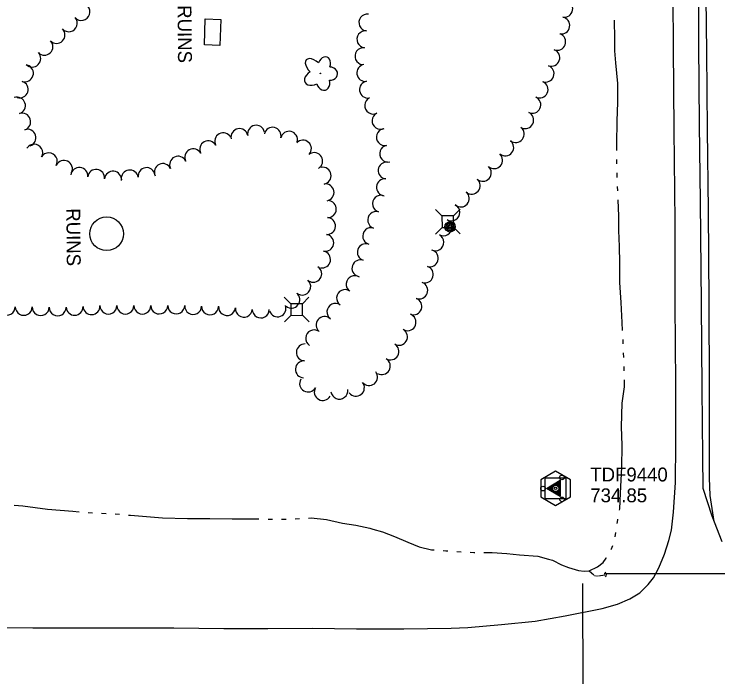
# Model space of a CAD drawing. Extents: x 589250 to 1188077, y 162953 to 363065.
# Drawn here: x 593849.7 to 594153.6, y 165056 to 165342.4 of the extents above; entities that cross this region are included whole.
import ezdxf

# ---------------------------------------------------------------- set-up
doc = ezdxf.new("R2010")
doc.units = 0
for name, color, linetype in [('E_BLD_HvyDash', 7, 'Continuous'), ('E_BLD_Text', 7, 'Continuous'), ('E_DRN', 7, 'Continuous'), ('E_DRN_Pipe', 7, 'Continuous'), ('E_LAND_TreeLine_P', 7, 'Continuous'), ('E_LAND_Vegetation', 7, 'Continuous'), ('E_MAP_Control', 7, 'Continuous'), ('E_MARK', 7, 'Continuous'), ('E_MISCPROP', 7, 'Continuous'), ('E_RDWY', 7, 'Continuous'), ('E_RDWY_Gravel', 7, 'Continuous'), ('E_UTL_AG_Bold', 7, 'Continuous'), ('E_WTR_FlowLine', 7, 'Continuous')]:
    doc.layers.add(name, color=color, linetype=linetype)

msp = doc.modelspace()

# ---------------------------------------------------------------- linework, layer by layer
at = {"layer": 'E_BLD_HvyDash'}
for p, q in [((593931.82, 165329.04), (593932.22, 165340.3)), ((593932.22, 165340.3), (593938.97, 165340.06)), ((593938.97, 165340.06), (593938.57, 165328.8)), ((593938.57, 165328.8), (593931.82, 165329.04))]:
    msp.add_line(p, q, dxfattribs=at)
msp.add_circle((593889.63, 165247.45), 7.29, dxfattribs=at)
at = {"layer": 'E_DRN'}
msp.add_arc((594104.16, 165100.16), 1.29, 311.5769, 57.8372, dxfattribs=at)
at = {"layer": 'E_DRN_Pipe'}
for p, q in [((594104.49, 165100.65), (594178.36, 165100.72)), ((594095.38, 165030.3), (594095.29, 165096.31))]:
    msp.add_line(p, q, dxfattribs=at)
at = {"layer": 'E_LAND_TreeLine_P'}
for centre, start, end in [((594087.23, 165344.67), 259.9627, 79.9627), ((593878.74, 165343.3), 221.885, 41.885), ((594002.23, 165338.73), 83.3272, 263.3272), ((593873.3, 165338.41), 221.885, 41.885), ((594085.96, 165337.46), 259.9627, 79.9627), ((593867.98, 165333.39), 224.3525, 44.3525), ((594001.37, 165331.46), 83.3272, 263.3272), ((594084.18, 165330.39), 249.9898, 69.9898), ((593862.75, 165328.27), 224.3525, 44.3525), ((594000.52, 165324.19), 83.3272, 263.3272), ((593857.52, 165323.16), 224.3525, 44.3525), ((594081.68, 165323.52), 249.9898, 69.9898), ((593854.33, 165316.78), 252.173, 72.173), ((594001.31, 165316.96), 99.1624, 279.1624), ((594079.17, 165316.64), 249.9898, 69.9898), ((593852.09, 165309.81), 252.173, 72.173), ((594002.47, 165309.74), 99.1624, 279.1624), ((594076.58, 165309.81), 244.7657, 64.7657), ((593850.89, 165302.85), 288.1174, 108.1174), ((594004.71, 165302.85), 115.8407, 295.8407), ((594073.46, 165303.19), 244.7657, 64.7657), ((594070.34, 165296.57), 244.7657, 64.7657), ((593853.16, 165295.89), 288.1174, 108.1174), ((594007.9, 165296.27), 115.8407, 295.8407), ((593954.16, 165290.69), 11.4466, 191.4466), ((593855.44, 165288.94), 288.1174, 108.1174), ((593939.95, 165287.42), 28.178, 208.178), ((593946.99, 165289.24), 11.4466, 191.4466), ((593961.29, 165289.8), 346.489, 166.489), ((593968.41, 165288.09), 346.489, 166.489), ((594009.79, 165289.24), 101.2182, 281.2182), ((594066.27, 165290.53), 231.9139, 51.9139), ((593933.5, 165283.97), 28.178, 208.178), ((593974.39, 165284.25), 317.4433, 137.4433), ((594061.76, 165284.78), 231.9139, 51.9139), ((593858.36, 165282.5), 329.2323, 149.2323), ((594011.21, 165282.07), 101.2182, 281.2182), ((593864.65, 165278.76), 329.2323, 149.2323), ((593927.05, 165280.51), 28.178, 208.178), ((593979.25, 165278.87), 300.9044, 120.9044), ((594056.95, 165279.26), 228.2496, 48.2496), ((593871.19, 165275.49), 334.2631, 154.2631), ((593920.48, 165277.3), 25.5755, 205.5755), ((594010.58, 165274.79), 84.0636, 264.0636), ((593877.82, 165272.46), 353.5773, 173.5773), ((593885.09, 165271.64), 353.5773, 173.5773), ((593906.86, 165272.38), 8.1699, 188.1699), ((593913.88, 165274.14), 25.5755, 205.5755), ((593982.89, 165272.55), 279.9789, 99.9789), ((594052.08, 165273.8), 228.2496, 48.2496), ((593892.36, 165270.82), 353.5773, 173.5773), ((593899.61, 165271.34), 8.1699, 188.1699), ((594009.82, 165267.52), 84.0636, 264.0636), ((594047.3, 165268.26), 229.5238, 49.5238), ((593984.16, 165265.34), 279.9789, 99.9789), ((594008.15, 165260.42), 73.0028, 253.0028), ((594042.55, 165262.69), 229.5238, 49.5238), ((593985.14, 165258.12), 267.2807, 87.2807), ((594006.01, 165253.43), 73.0028, 253.0028), ((594038.47, 165256.67), 241.9399, 61.9399), ((593984.8, 165250.81), 267.2807, 87.2807), ((594035.03, 165250.22), 241.9399, 61.9399), ((594003.87, 165246.43), 73.0028, 253.0028), ((593984.05, 165243.55), 258.8555, 78.8555), ((594031.58, 165243.76), 241.9399, 61.9399), ((594001.56, 165239.49), 71.3881, 251.3881), ((593982.64, 165236.37), 258.8555, 78.8555), ((594029.19, 165236.87), 252.9461, 72.9461), ((593999.23, 165232.55), 71.3881, 251.3881), ((593978.84, 165230.18), 236.0753, 56.0753), ((594027.05, 165229.87), 252.9461, 72.9461), ((593974.09, 165224.62), 229.1768, 49.1768), ((593996.73, 165225.7), 55.3204, 235.3204), ((594024.63, 165222.97), 249.7043, 69.7043), ((593969.42, 165218.99), 230.8494, 50.8494), ((593992.57, 165219.68), 55.3204, 235.3204), ((594022.1, 165216.1), 249.7043, 69.7043), ((593846.52, 165215.98), 179.202, 359.202), ((593853.84, 165215.88), 179.202, 359.202), ((593861.16, 165215.78), 179.202, 359.202), ((593868.47, 165215.68), 179.202, 359.202), ((593875.79, 165215.91), 182.2098, 2.2098), ((593883.1, 165216.19), 182.2098, 2.2098), ((593890.41, 165216.41), 180.1719, 0.1719), ((593897.73, 165216.43), 180.1719, 0.1719), ((593905.04, 165216.45), 180.1719, 0.1719), ((593912.36, 165216.47), 180.1719, 0.1719), ((593919.68, 165216.49), 180.1719, 0.1719), ((593926.99, 165216.29), 178.2791, 358.2791), ((593934.31, 165216.07), 178.2791, 358.2791), ((593941.62, 165215.8), 174.488, 354.488), ((593948.9, 165215.1), 174.488, 354.488), ((593956.2, 165214.75), 179.3224, 359.3224), ((593963.42, 165215.24), 200.6386, 20.6386), ((593988.4, 165213.67), 55.3204, 235.3204), ((593983.75, 165208.03), 50.0604, 230.0604), ((594019.56, 165209.24), 249.7043, 69.7043), ((593979.24, 165202.27), 55.9366, 235.9366), ((594015.88, 165202.92), 239.6076, 59.6076), ((593975.21, 165196.18), 87.0023, 267.0023), ((594012.17, 165196.61), 239.6076, 59.6076), ((594008.47, 165190.3), 239.6076, 59.6076), ((593974.83, 165188.88), 87.0023, 267.0023), ((594002.97, 165185.54), 218.7977, 38.7977), ((593976.62, 165182.75), 150.0782, 330.0782), ((593997.27, 165180.95), 218.7977, 38.7977), ((593982.96, 165179.1), 150.0782, 330.0782), ((593990.14, 165179.69), 187.5775, 7.5775)]:
    msp.add_arc(centre, 3.66, start, end, dxfattribs=at)
at = {"layer": 'E_LAND_Vegetation'}
msp.add_circle((593981.95, 165316.76), 0.128, dxfattribs=at)
for centre, major_axis, ratio in [((593983.58, 165320.43), (-1.27, -3.4), 0.716896), ((593979.35, 165319.36), (3.5, -3.21), 0.560249), ((593985.93, 165316.64), (-3.45, 0.09), 0.832022), ((593978.98, 165314.85), (3.69, 2.04), 0.691916), ((593983.13, 165313.03), (-0.94, 3.49), 0.782863)]:
    msp.add_ellipse(centre, major_axis=major_axis, ratio=ratio, start_param=1.570796, end_param=4.712389, dxfattribs=at)
at = {"layer": 'E_MAP_Control'}
for p, q in [((594078.98, 165132.94), (594078.98, 165141.94)), ((594078.98, 165141.94), (594087.98, 165141.94)), ((594087.98, 165141.94), (594087.98, 165132.94)), ((594087.98, 165132.94), (594078.98, 165132.94))]:
    msp.add_line(p, q, dxfattribs=at)
msp.add_lwpolyline([(594077.07, 165141.2), (594077.07, 165133.81), (594083.52, 165130.09), (594089.92, 165133.75), (594089.92, 165141.08), (594083.4, 165144.81)], close=True, dxfattribs=at)
msp.add_circle((594083.48, 165137.44), 0.546, dxfattribs=at)
at = {"layer": 'E_MARK'}
for p, q in [((594079.56, 165137.38), (594085.5, 165140.94)), ((594079.84, 165137.39), (594085.34, 165140.66)), ((594080.2, 165137.39), (594085.18, 165140.38)), ((594080.48, 165137.39), (594085.03, 165140.1)), ((594080.76, 165137.39), (594084.87, 165139.82)), ((594084.87, 165139.82), (594084.9, 165135.02)), ((594084.87, 165139.82), (594084.87, 165139.82)), ((594085.03, 165140.1), (594085.06, 165134.78)), ((594085.03, 165140.1), (594085.03, 165140.1)), ((594085.18, 165140.38), (594085.22, 165134.54)), ((594085.18, 165140.38), (594085.18, 165140.38)), ((594085.34, 165140.66), (594085.38, 165134.22)), ((594085.34, 165140.66), (594085.34, 165140.66)), ((594085.5, 165140.94), (594085.54, 165133.98)), ((594085.5, 165140.94), (594085.5, 165140.94)), ((594085.54, 165133.98), (594079.56, 165137.38)), ((594085.38, 165134.22), (594079.84, 165137.39)), ((594085.22, 165134.54), (594080.2, 165137.39)), ((594085.06, 165134.78), (594080.48, 165137.39)), ((594084.9, 165135.02), (594080.76, 165137.39))]:
    msp.add_line(p, q, dxfattribs=at)
for centre, radius in [((594086.22, 165142.15), 1), ((594083.52, 165137.41), 2), ((594083.52, 165137.41), 1.84), ((594083.52, 165137.41), 1.68), ((594083.52, 165137.41), 1.52), ((594083.52, 165137.41), 1.36), ((594078.06, 165137.37), 1), ((594086.28, 165132.7), 1)]:
    msp.add_circle(centre, radius, dxfattribs=at)
at = {"layer": 'E_MISCPROP'}
for radius in [2.23, 1.67, 1.12, 0.558]:
    msp.add_circle((594037.94, 165250.43), radius, dxfattribs=at)
at = {"layer": 'E_RDWY'}
for p, q in [((594145.09, 165365.2), (594145.23, 165329.35)), ((594134.4, 165327.93), (594134.29, 165360.98)), ((594134.68, 165292.39), (594134.4, 165327.93)), ((594145.23, 165329.35), (594145.52, 165294.67)), ((594145.52, 165294.67), (594145.99, 165261.47)), ((594135.08, 165252.57), (594134.68, 165292.39)), ((594145.99, 165261.47), (594146.44, 165217.14)), ((594135.17, 165217.23), (594135.08, 165252.57)), ((594135.43, 165182.66), (594135.17, 165217.23)), ((594146.44, 165217.14), (594146.71, 165180.61)), ((594135.41, 165156.67), (594135.43, 165182.66)), ((594146.71, 165180.61), (594146.89, 165151.17)), ((594135.22, 165140.01), (594135.41, 165156.67)), ((594146.89, 165151.17), (594147.16, 165137.47)), ((594134.43, 165127.15), (594135.22, 165140.01)), ((594147.16, 165137.47), (594150.97, 165125.56)), ((594133.55, 165119.37), (594134.43, 165127.15)), ((594150.97, 165125.56), (594155.3, 165114.44)), ((594132.46, 165114.94), (594133.55, 165119.37)), ((594130.53, 165109.01), (594132.46, 165114.94)), ((594128.11, 165103.13), (594130.53, 165109.01)), ((594125.73, 165098.75), (594128.11, 165103.13)), ((594123.44, 165095.85), (594125.73, 165098.75)), ((594119.82, 165092.24), (594123.44, 165095.85)), ((594115.62, 165089.66), (594119.82, 165092.24)), ((594103.64, 165085.51), (594110.21, 165087.38)), ((594110.21, 165087.38), (594115.62, 165089.66)), ((594087.7, 165082.44), (594103.64, 165085.51)), ((594074.71, 165080.1), (594087.7, 165082.44)), ((594045.67, 165077.35), (594060.16, 165078.57)), ((594060.16, 165078.57), (594074.71, 165080.1)), ((593839.04, 165077.43), (593857.76, 165077.18)), ((593857.76, 165077.18), (593874.69, 165077.19)), ((593874.69, 165077.19), (593896.06, 165077.16)), ((593896.06, 165077.16), (593918.59, 165077.21)), ((593918.59, 165077.21), (593940.21, 165076.97)), ((593940.21, 165076.97), (593959.18, 165076.85)), ((593959.18, 165076.85), (593978.57, 165077.02)), ((593978.57, 165077.02), (593997.51, 165076.8)), ((593997.51, 165076.8), (594017.94, 165076.75)), ((594017.94, 165076.75), (594038.37, 165077.02)), ((594038.37, 165077.02), (594045.67, 165077.35))]:
    msp.add_line(p, q, dxfattribs=at)
at = {"layer": 'E_RDWY_Gravel'}
for p, q in [((594148.23, 165361.77), (594148.67, 165325.73)), ((594148.67, 165325.73), (594149, 165292.32)), ((594149, 165292.32), (594149.45, 165257.44)), ((594149.45, 165257.44), (594149.62, 165217.85)), ((594149.62, 165217.85), (594149.79, 165180.82)), ((594149.79, 165180.82), (594149.78, 165142.06)), ((594149.78, 165142.06), (594150.08, 165134.3)), ((594150.08, 165134.3), (594151.91, 165123.14))]:
    msp.add_line(p, q, dxfattribs=at)
at = {"layer": 'E_UTL_AG_Bold'}
for p, q in [((594034.45, 165255.16), (594031.6, 165257.96)), ((594039.45, 165255.2), (594042.26, 165258.05)), ((594039.45, 165255.2), (594034.45, 165255.16)), ((594034.45, 165255.16), (594034.49, 165250.16)), ((594039.49, 165250.2), (594039.45, 165255.2)), ((594034.49, 165250.16), (594031.69, 165247.3)), ((594034.49, 165250.16), (594039.49, 165250.2)), ((594039.49, 165250.2), (594042.35, 165247.39)), ((593969.16, 165217.2), (593966.31, 165220)), ((593974.16, 165217.24), (593976.97, 165220.09)), ((593974.16, 165217.24), (593969.16, 165217.2)), ((593969.16, 165217.2), (593969.21, 165212.2)), ((593974.21, 165212.24), (593974.16, 165217.24)), ((593969.21, 165212.2), (593966.4, 165209.34)), ((593969.21, 165212.2), (593974.21, 165212.24)), ((593974.21, 165212.24), (593977.06, 165209.43))]:
    msp.add_line(p, q, dxfattribs=at)
at = {"layer": 'E_WTR_FlowLine'}
for p, q in [((594108.89, 165339.11), (594108.9, 165339.8)), ((594109.05, 165332.19), (594108.89, 165339.11)), ((594109.15, 165326.54), (594109.05, 165332.19)), ((594109.48, 165321.31), (594109.15, 165326.54)), ((594110.36, 165312.38), (594109.48, 165321.31)), ((594110.37, 165311.64), (594110.36, 165312.38)), ((594110.42, 165304.15), (594110.37, 165311.64)), ((594110.04, 165296.23), (594110.42, 165304.15)), ((594109.88, 165286.17), (594110.04, 165296.23)), ((594109.91, 165283.45), (594109.88, 165286.17)), ((594109.99, 165277.61), (594109.95, 165279.56)), ((594110.09, 165271.77), (594110.05, 165273.72)), ((594110.35, 165265.94), (594110.26, 165267.89)), ((594110.76, 165255.02), (594110.5, 165262.06)), ((594110.88, 165248.93), (594110.76, 165255.02)), ((594111.13, 165241.9), (594110.88, 165248.93)), ((594111.27, 165234.83), (594111.13, 165241.9)), ((594111.25, 165226.4), (594111.27, 165233.86)), ((594111.27, 165233.86), (594111.27, 165234.83)), ((594111.84, 165217.73), (594111.25, 165226.4)), ((594112.23, 165209.07), (594111.84, 165217.73)), ((594112.42, 165205.68), (594112.23, 165209.07)), ((594112.75, 165199.93), (594112.64, 165201.8)), ((594112.75, 165199.85), (594112.75, 165199.93)), ((594112.96, 165194.02), (594112.89, 165195.97)), ((594113.12, 165189.71), (594113.11, 165190.13)), ((594113.14, 165188.19), (594113.12, 165189.71)), ((594113.24, 165181.28), (594113.2, 165184.3)), ((594112.22, 165174.3), (594113.24, 165181.28)), ((594111.99, 165164.06), (594112.22, 165174.3)), ((594112.3, 165156.17), (594111.99, 165164.06)), ((594112.13, 165146.65), (594112.31, 165155.76)), ((594112.31, 165155.76), (594112.3, 165156.17)), ((594111.58, 165135.39), (594112.13, 165146.65)), ((594111.19, 165128.6), (594111.58, 165135.39)), ((593849.65, 165130.21), (593853.38, 165129.89)), ((593853.38, 165129.89), (593864.02, 165128.45)), ((593864.02, 165128.45), (593875.09, 165127.55)), ((593875.09, 165127.55), (593877.7, 165127.31)), ((593881.58, 165127.03), (593883.53, 165126.94)), ((593887.42, 165126.75), (593889.36, 165126.66)), ((593893.24, 165126.44), (593895.18, 165126.26)), ((594111.09, 165128), (594111.19, 165128.6)), ((593899.05, 165125.9), (593900, 165125.81)), ((593900, 165125.81), (593913.8, 165124.7)), ((593913.8, 165124.7), (593924.5, 165124.45)), ((593924.5, 165124.45), (593927.21, 165124.43)), ((593927.21, 165124.43), (593934.12, 165124.37)), ((593934.12, 165124.37), (593943.77, 165124.29)), ((593943.77, 165124.29), (593952.64, 165124.31)), ((593952.64, 165124.31), (593955.42, 165124.25)), ((593959.31, 165124.17), (593961.26, 165124.12)), ((593965.15, 165124.14), (593967.09, 165124.14)), ((593970.98, 165124.24), (593972.92, 165124.36)), ((593976.81, 165124.6), (593977.98, 165124.68)), ((593977.98, 165124.68), (593984.64, 165123.94)), ((593984.64, 165123.94), (593991.46, 165122.36)), ((594110.15, 165122.26), (594110.37, 165123.83)), ((594110.37, 165123.83), (594110.43, 165124.17)), ((593991.46, 165122.36), (593997.22, 165121.54)), ((593997.22, 165121.54), (594003.34, 165120.23)), ((594003.34, 165120.23), (594004.53, 165119.88)), ((594004.53, 165119.88), (594008.72, 165118.65)), ((594008.72, 165118.65), (594013.99, 165116.65)), ((594109.16, 165116.53), (594109.59, 165118.43)), ((594013.99, 165116.65), (594019.63, 165114.14)), ((594019.63, 165114.14), (594024.52, 165112.14)), ((594024.52, 165112.14), (594029.98, 165110.9)), ((594107.4, 165110.99), (594107.62, 165111.38)), ((594107.62, 165111.38), (594108.17, 165112.77)), ((594029.98, 165110.9), (594031.11, 165110.82)), ((594034.99, 165110.54), (594036.1, 165110.46)), ((594036.1, 165110.46), (594036.93, 165110.41)), ((594040.81, 165110.13), (594042.75, 165109.99)), ((594046.63, 165109.84), (594048.15, 165109.79)), ((594048.15, 165109.79), (594048.58, 165109.79)), ((594052.47, 165109.79), (594056.12, 165109.78)), ((594056.12, 165109.78), (594062.5, 165109.3)), ((594062.5, 165109.3), (594067.94, 165108.75)), ((594067.94, 165108.75), (594075.87, 165108.14)), ((594075.87, 165108.14), (594080.43, 165106.88)), ((594080.43, 165106.88), (594082.15, 165106.4)), ((594082.15, 165106.4), (594086, 165104.39)), ((594101.55, 165103.5), (594104.02, 165105.48)), ((594104.02, 165105.48), (594105.36, 165107.29)), ((594105.36, 165107.29), (594105.52, 165107.58)), ((594086, 165104.39), (594089.1, 165103.29)), ((594089.1, 165103.29), (594093.4, 165102.02)), ((594098.01, 165101.83), (594101.55, 165103.5)), ((594093.4, 165102.02), (594095.78, 165101.66)), ((594095.78, 165101.66), (594098.01, 165101.83)), ((594098.06, 165101.86), (594100.09, 165100.05)), ((594100.37, 165099.8), (594100.38, 165099.79)), ((594100.38, 165099.79), (594100.55, 165099.77)), ((594100.93, 165099.72), (594101.11, 165099.7)), ((594101.49, 165099.66), (594101.67, 165099.64)), ((594102.04, 165099.61), (594104.72, 165100.11))]:
    msp.add_line(p, q, dxfattribs=at)

# ---------------------------------------------------------------- texts
at = {"layer": 'E_BLD_Text'}
for p in [(593920.25, 165346.18), (593872.22, 165258.44)]:
    msp.add_text('RUINS', height=6, rotation=270.4812, dxfattribs=at).set_placement(p)
at = {"layer": 'E_MAP_Control'}
for s, p in [('TDF9440', (594098.49, 165140.44)), ('734.85', (594098.49, 165131.44))]:
    msp.add_text(s, height=6, dxfattribs=at).set_placement(p)

doc.saveas('drawing.dxf')
